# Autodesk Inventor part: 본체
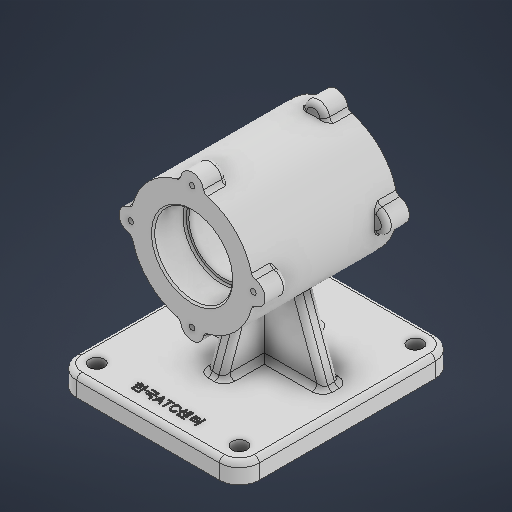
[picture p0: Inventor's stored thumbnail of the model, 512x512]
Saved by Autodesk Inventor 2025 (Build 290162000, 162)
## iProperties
Created: 2025-08
Part Number: 본체
Material: 일반
Document SubType Name: Modeling
Designer: infra005
Density: 1 g/cm^3
Appearance: 기본값
Author: infra005
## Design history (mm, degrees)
sketch "스케치1"
  geometry: L1 (55, 65)-(-55, 65); L2 (-55, 65)-(-55, -65); L3 (-55, -65)-(55, -65); L4 (55, -65)-(55, 65); L5 (55, 65)-(-55, -65); L6 (-55, 65)-(55, -65); 1 further point
  constraints: 12 end point, 2 midpoint, 2 parallel, 1 horizontal, 1 perpendicular
  dimensions: "d0" = 110 distance of L3.end L2.end; "d1" = 130 distance of L2.end L1.end
extrude "돌출1" new body sketch "스케치1" distance "d2" = 12; taper "d3" = 0 deg
sketch "스케치2"
  geometry: L1 (-55, -65)-(55, -65) reference; L2 (-55, 65)-(-55, -65) reference; L3 (0, 0)-(-113.867, 0); L4 (0, 0)-(0, 97.396); L5 (0, 0)-(113.867, 0); L6 (55, 65)-(-55, 65) reference; L7 (55, -65)-(55, 65) reference; L8 (55, 65)-(-55, 65) reference; L9 (-55, 65)-(-55, -65) reference; L10 (-55, -65)-(55, -65) reference; C1 r 4.5 at (-43, -53); C2 r 4.5 at (-43, 53); C3 r 4.5 at (43, -53); C4 r 4.5 at (43, 53)
  constraints: 6 end point, 4 centre point, 4 symmetric about line, 1 horizontal, 1 vertical, 3 other
  dimensions: "d4" = 9 diameter of C1; "d8" = 12 distance from line of L6 C2.centre; "d9" = 86 distance of C2.centre C4.centre
extrude "돌출2" cut sketch "스케치2" extent not by distance; stored distance "d10" = 0; taper "d11" = 0 deg
sketch "스케치3"
  geometry: L1 (0, -65)-(0, 65) reference; L2 (105.5, 38.5)-(105.5, 19.5); L3 (105.5, 38.5)-(119, 38.5); L4 (119, 38.5)-(119, -48.5); L5 (119, -48.5)-(105.5, -48.5); L6 (105.5, -48.5)-(105.5, -29.5); L7 (105.5, -29.5)-(82, -29.5); L8 (82, -29.5)-(82, 19.5); L9 (82, 19.5)-(105.5, 19.5); L10 (119, -5)-(82, -5); L11 (0, 65)-(12, 65) reference; 1 further point
  constraints: 18 end point, 5 perpendicular, 2 midpoint, 2 vertical
  dimensions: "d17" = 19 distance of L2.start L2.end; "d18" = 13.5 distance of L2.start L3.end; "d19" = 87 distance of L3.end L4.end; "d20" = 19 distance of L5.end L6.end; "d21" = 70 distance between parallel lines of L10 L11; "d22" = 82 distance between parallel lines of L1 L8; "d23" = 23.5 distance of L8.end L2.end; "d24" = 13.5 distance between parallel lines of L4 L6
revolve "회전1" sketch "스케치3" stored, may be unused: angle "d25" = 90 deg
sketch "스케치4"
  geometry: C1 r 23.5 at (0, 0) reference; C2 r 21 at (0, 0); 1 further point
  constraints: 1 centre point, 1 coincident
  dimensions: "d26" = 42 diameter of C2
extrude "돌출3" cut sketch "스케치4" extent not by distance; stored distance "d27" = 0; taper "d28" = 0 deg
sketch "스케치5"
  geometry: L1 (0, 0)-(0, 72.178); L2 (0, 0)-(-65.912, 0); C1 r 7 at (0, 37); C2 r 7 at (-37, 0); C3 r 7 at (0, -37); C4 r 7 at (37, 0); 1 further point
  constraints: 4 centre point, 4 end point, 1 horizontal, 1 point on line, 1 vertical, 1 vertical alignment, 10 other
  dimensions: "d29" = 14 diameter of C1; "d32" = 360 deg dimension on L1.start C1.centre (derived)
extrude "돌출4" join sketch "스케치5" distance "d34" = 14; taper "d35" = 0 deg
sketch "스케치6"
  geometry: A1 r 7 centre (0, 37) between (6.969, 36.338) and (-6.969, 36.338) reference; A2 r 7 centre (-37, 0) between (-36.338, 6.969) and (-36.338, -6.969) reference; A3 r 7 centre (37, 0) between (36.338, -6.969) and (36.338, 6.969) reference; A4 r 7 centre (0, -37) between (-6.969, -36.338) and (6.969, -36.338) reference; 2 further points
  constraints: 1 other
extrude "돌출5" join sketch "스케치6" distance "d36" = 14; taper "d37" = 0 deg
node "작업 평면1"
sketch "스케치8"
  geometry: L1 (0, 12)-(110, 12) reference; L2 (14, 12)-(29.664, 55.036); L3 (0, 0)-(0, 12) reference; L4 (55, 82)-(55, 0); L5 (96, 12)-(80.336, 55.036); L6 (29.664, 55.036)-(80.336, 55.036); A1 r 37 centre (55, 82) between (18.662, 75.031) and (48.031, 45.662) reference; A2 r 37 centre (55, 82) between (61.969, 45.662) and (91.338, 75.031) reference; 1 further point
  constraints: 8 end point, 2 symmetric about line, 1 horizontal, 1 point on circle, 1 point on line, 1 vertical
  dimensions: "d40" = 110 deg angle of L1 L2; "d41" = 14 distance from line of L2.start L3
extrude "돌출6" join sketch "스케치8" stored distance "d42" = 10; taper "d43" = 0 deg
sketch "스케치9"
  geometry: L1 (12, -65)-(12, 65) reference; L2 (12, -35)-(45, -22.989); L3 (45, -34.5)-(45, 24.5) reference; L4 (45, 12.989)-(12, 25); L5 (119, -34.5)-(119, 24.5) reference; L6 (119, -5)-(-33.779, -5); 1 further point
  constraints: 6 end point, 4 point on line, 1 midpoint, 1 other
  dimensions: "d44" = 60 distance of L4.end L2.start; "d45" = 110 deg angle of L1 L2; "d46" = 110 deg angle of L1 L4
extrude "돌출7" join sketch "스케치9" stored distance "d47" = 10; taper "d48" = 0 deg
sketch "스케치10"
  geometry: L1 (0, 0)-(-5, 0) reference; A1 r 7 centre (0, 74) between (6.969, 73.338) and (-6.969, 73.338) reference; A2 r 7 centre (-37, 37) between (-36.338, 43.969) and (-36.338, 30.031) reference; A3 r 7 centre (0, 0) between (-6.969, 0.662) and (6.969, 0.662) reference; A4 r 7 centre (37, 37) between (36.338, 30.031) and (36.338, 43.969) reference; 5 further points
  constraints: 4 coincident
hole "구멍1" sketch "스케치10" at (0, 74), (-37, 37), (0, 0), (37, 37) diameter "d49" = 3.242; stored, may be unused: countersink angle "d53" = 90 deg, drill point angle "d55" = 118 deg; dims "d50" = 8, "d51" = 4, "d52" = 2, "d54" = 10
sketch "스케치11"
  geometry: C1 r 1.621 at (37, -37) reference; A1 r 7 centre (0, 0) between (6.969, -0.662) and (-6.969, -0.662) reference; A2 r 7 centre (-37, -37) between (-36.338, -30.031) and (-36.338, -43.969) reference; A3 r 7 centre (0, -74) between (-6.969, -73.338) and (6.969, -73.338) reference; A4 r 7 centre (37, -37) between (36.338, -43.969) and (36.338, -30.031) reference; 5 further points
  constraints: 4 coincident
hole "구멍2" sketch "스케치11" at (-37, -37), (0, 0), (37, -37), (0, -74) diameter "d56" = 3.242; stored, may be unused: countersink angle "d60" = 90 deg, drill point angle "d62" = 118 deg; dims "d57" = 8, "d58" = 4, "d59" = 2, "d61" = 10
fillet "모깎기1" dims "d63" = 12
fillet "모깎기2" dims "d64" = 1
fillet "모깎기3" dims "d65" = 3
fillet "모깎기4" dims "d66" = 3
node "작업 평면2"
sketch "스케치13"
  geometry: L1 (-20.838, -48.015)-(20.838, -48.015); L2 (20.838, -48.015)-(20.838, -57.985); L3 (20.838, -57.985)-(-20.838, -57.985); L4 (-20.838, -57.985)-(-20.838, -48.015); L5 (-20.838, -53)-(20.838, -53); L6 (0, -48.015)-(0, -57.985); L7 (-43, -65)-(43, -65) reference; L8 (0, -65)-(0, 108.668); L9 (-43.101, 7)-(-43.101, 3) reference; L10 (-43.101, 5)-(43.101, 5); L11 (43.101, 3)-(43.101, 7) reference; 3 further points
  constraints: 9 midpoint, 8 end point, 1 vertical, 1 vertical alignment, 2 other
  dimensions: "d68" = 58 distance from line of point (0, -53) L10
feature "엠보싱1" sketch "스케치13" dims "d0" = 110, "d1" = 130, "d69" = 0.5, "d70" = 0
chamfer "모따기1" distance "d71" = 1; stored, may be unused: second distance "d72" = 2, angle "d73" = 45 deg
chamfer "모따기2" distance "d74" = 1; stored, may be unused: second distance "d75" = 2, angle "d76" = 45 deg
node "솔리드1"
node "투영된 루프1"
node "스케치 - 원형 패턴1" dims "d32" = 360 deg (derived)
feature "A9D066F2-1C7D-4E18-AEED-F7BC21143FA4" dims "d49" = 3.242, "d50" = 8, "d51" = 4, "d52" = 2, "d53" = 90 deg, "d54" = 10, "d55" = 118 deg
other parameters: "d67" = 0.5
